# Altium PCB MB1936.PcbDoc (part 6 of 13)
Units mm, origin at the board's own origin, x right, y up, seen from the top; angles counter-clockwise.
Board outline 172 x 137 mm, 6 copper layers (Top Layer, Signal Layer 1, Signal Layer 2, Signal Layer 3, Signal Layer 4, Bottom Layer), stack 1.549 mm thick; 859 components, 672 nets, 3477 pads, 2222 vias.
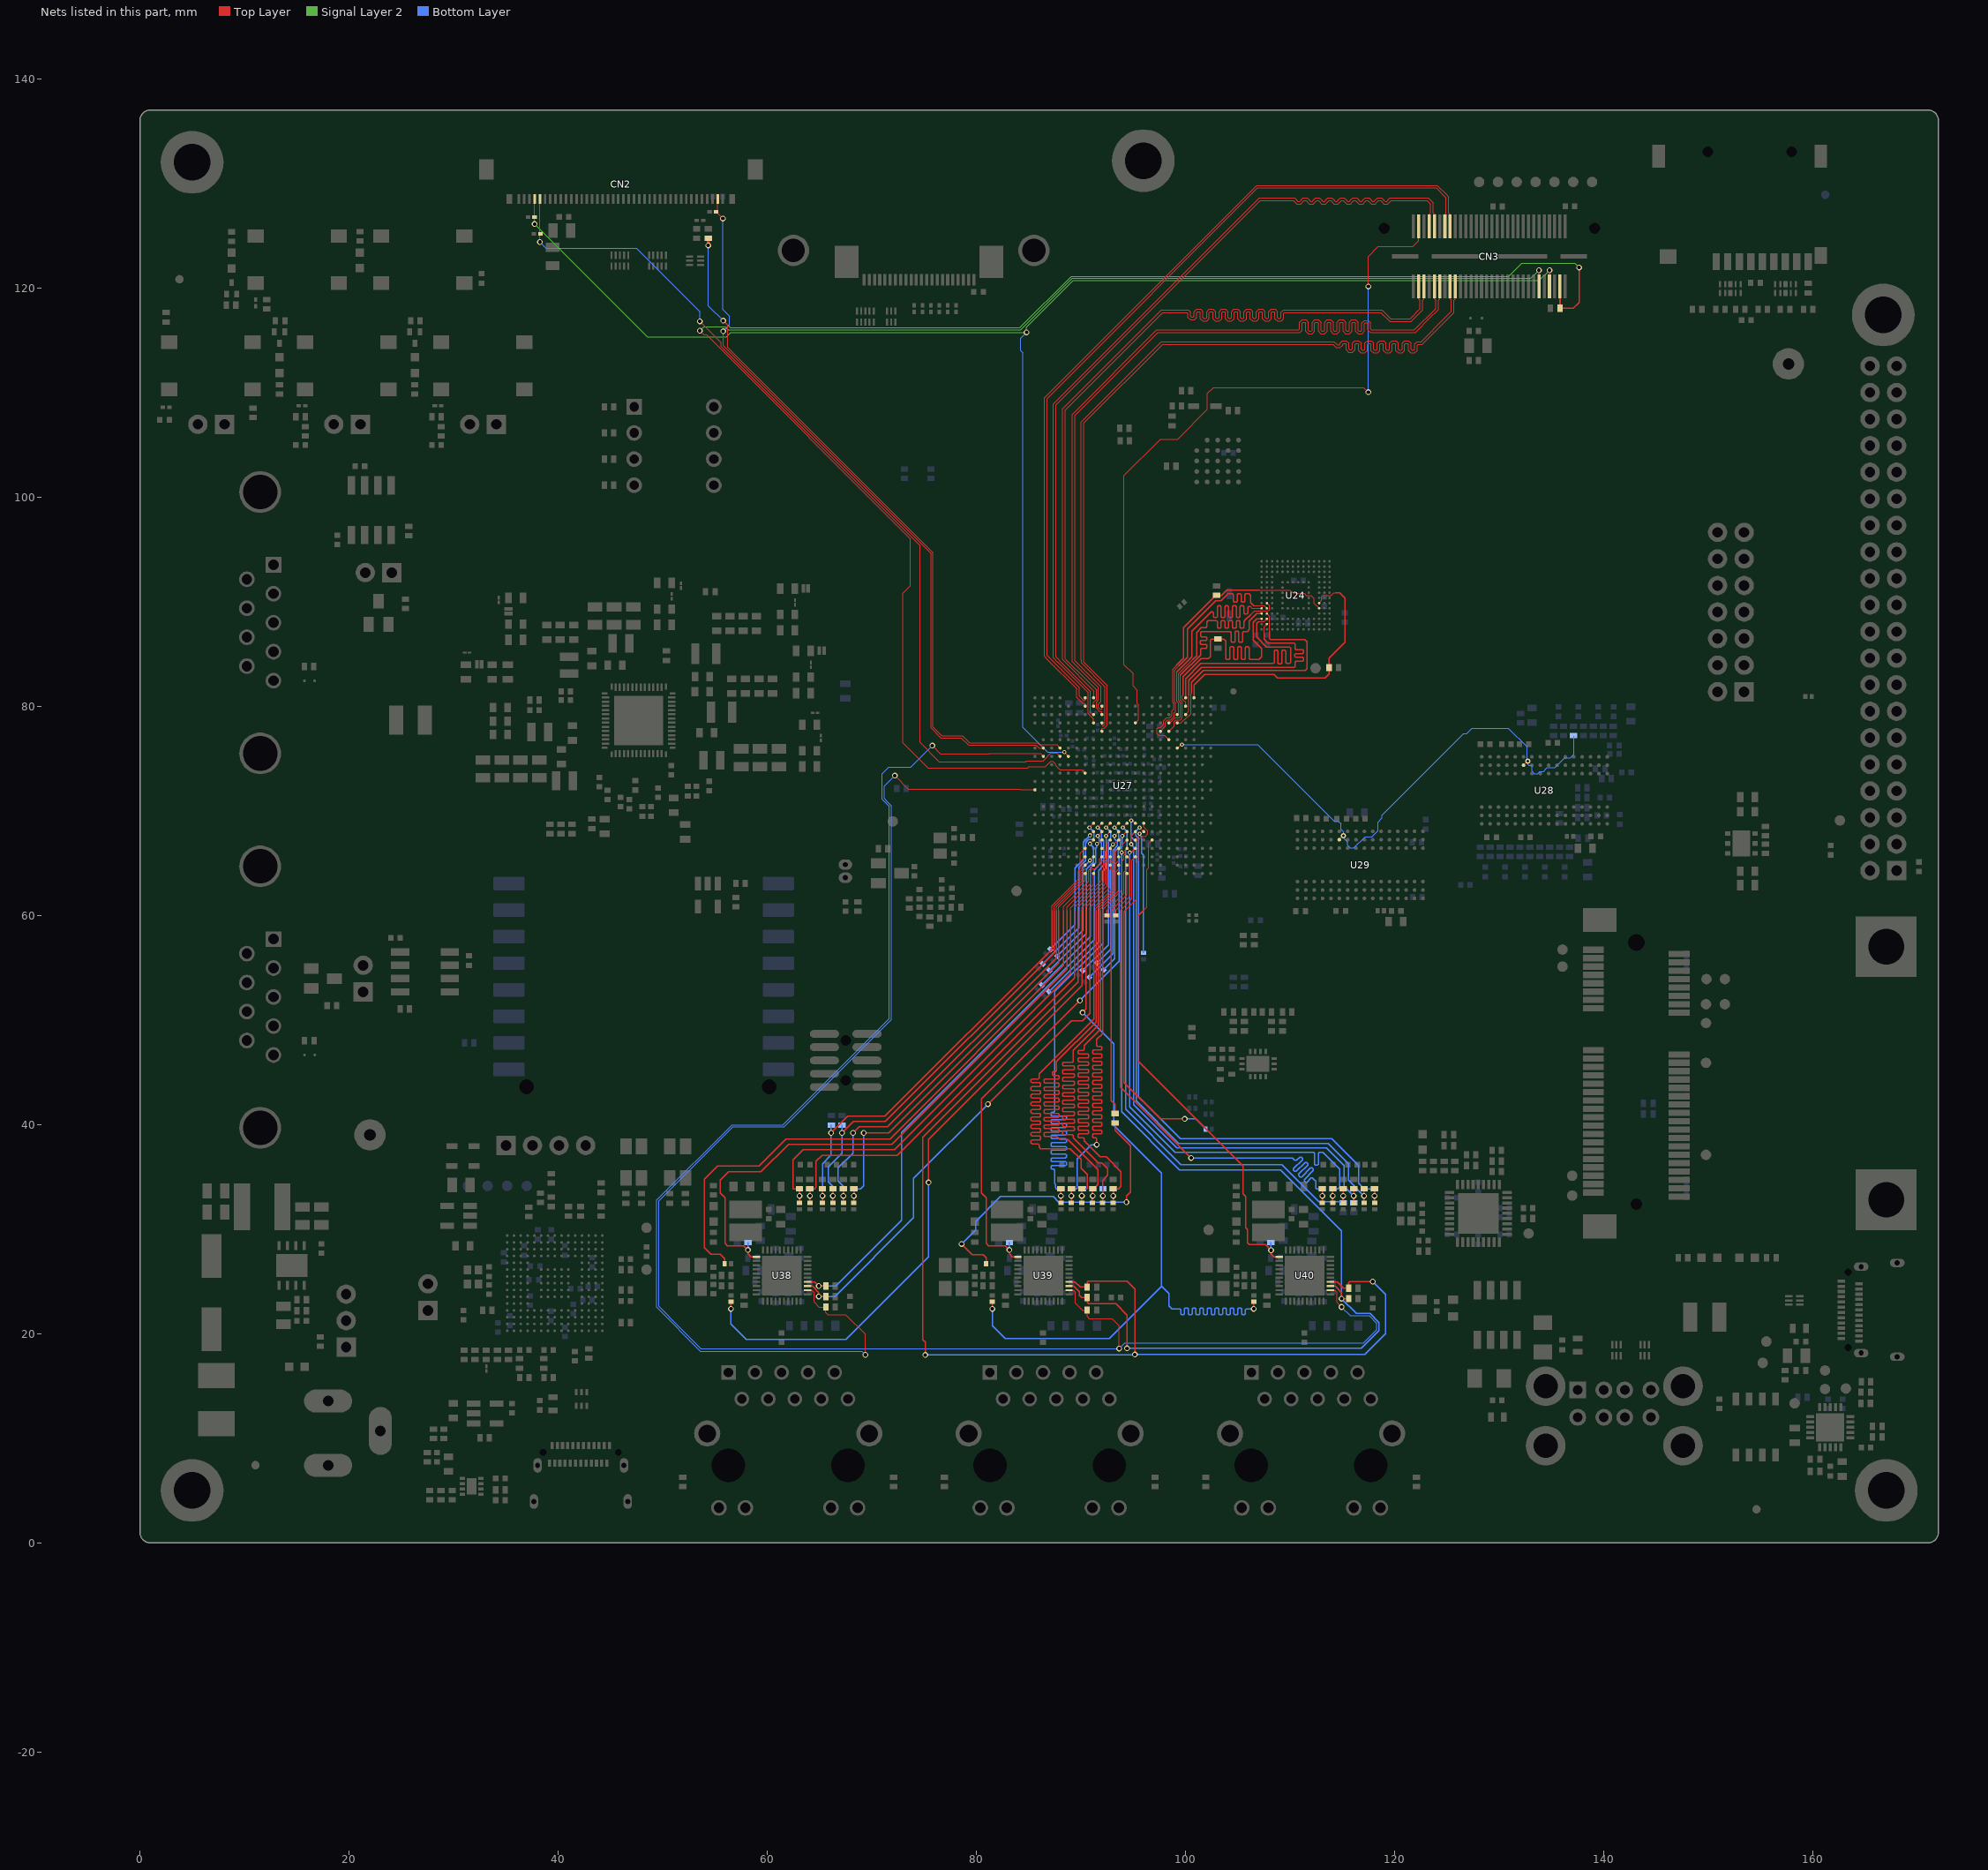
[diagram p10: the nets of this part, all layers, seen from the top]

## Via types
v1: diameter 0.55, hole 0.35, Top Layer to Bottom Layer, 1661 vias
v2: diameter 0.4, hole 0.2, Top Layer to Bottom Layer, tented both sides, 253 vias
v3: diameter 0.5, hole 0.2, Top Layer to Bottom Layer, 157 vias
v4: diameter 0.5, hole 0.25, Top Layer to Bottom Layer, 145 vias
v5: diameter 0.4, hole 0.2, Top Layer to Bottom Layer, 6 vias

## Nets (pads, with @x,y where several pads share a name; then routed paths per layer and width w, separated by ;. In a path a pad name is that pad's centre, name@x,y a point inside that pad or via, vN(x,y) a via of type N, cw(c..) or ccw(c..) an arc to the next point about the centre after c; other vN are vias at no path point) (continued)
DDR_WEN: R257.1 U27.G18 U28.L2 U29.L2 | length 55
  Top Layer w0.09: U27.G18@99.2,76 99.257,76 99.582,76.325 v2(99.65,76.325) ; U29.L2@114.694,67.222 114.694,67.27 v4@115.049,67.625 ; U28.L2@132.325,74.325 132.325,74.373 v4@132.68,74.728
  Bottom Layer w0.09: v2(99.65,76.325) 99.666,76.341 106.877,76.341 114.223,68.995 114.614,68.995 114.845,68.764 114.845,68.223 115.1,67.968 v4(115.1,67.625) ; v4@115.102,67.625 115.162,67.566 115.162,67.322 115.505,66.979 115.505,66.684 115.737,66.453 116.098,66.453 117.165,67.52 117.824,67.52 118.388,68.084 118.388,68.909 118.395,68.909 118.794,69.308 118.794,69.555 126.602,77.363 126.878,77.363 127.412,77.897 130.872,77.897 132.662,76.107 132.662,74.813 v4(132.725,74.75) 132.725,74.458 132.839,74.345 133.032,74.345 133.124,74.253 133.124,73.793 133.362,73.555 133.689,73.555 133.885,73.751 134.227,73.751 134.585,74.11 135.319,74.11 136.274,75.065 136.799,75.065 137.135,75.401 137.135,77.141 R257.1@137.1,77.175
DISP.BLCTRL: CN2.37 CN3.53 U2.1 U27.H5 | length 152
  Top Layer w0.1: v1(37.75,126.1) CN2.37@37.75,128.5 ; v2(88.4,75.6) U27.H5@88.8,75.2 ; CN3.53@134.8,120.13 v1(134.8,121.675)
  Signal Layer 2 w0.1: v1(37.75,126.1) 48.525,115.325 56.1,115.325 56.525,115.75 v1(84.8,115.75) 84.8,116.25 89.25,120.7 133.825,120.7 v1(134.8,121.675)
  Bottom Layer w0.1: v1(84.8,115.75) 84.225,115.175 84.225,113.999 84.45,113.774 84.45,77.955 86.806,75.6 v2(88.4,75.6)
DISP.DSI_INT: CN3.4 U27.D13 | length 72
  Top Layer w0.1: U27.D13@95.2,78.4 95.49,78.69 95.49,80.141 95.385,80.246 95.385,81.515 94.975,81.925 94.975,83.1 94.125,83.95 94.125,84.475 94.125,102.051 97.599,105.525 99.248,105.525 102.1,108.377 102.1,109.917 102.658,110.475 117.025,110.475 v1(117.475,110.025) ; v1(117.475,120.125) 117.475,123 118.42,123.945 121.72,123.945 122.3,124.525 CN3.4@122.3,125.87
  Bottom Layer w0.1: v1(117.475,110.025) v1(117.475,120.125)
DISP.LED_EN: CN2.36 U4.1 U27.H4 | length 86.7
  Top Layer w0.09: 81.172,74.685 84.727,74.685 84.787,74.745 86.364,74.745 86.796,75.177 86.796,75.213 87.088,75.505 87.695,75.505 U27.H4@88,75.2
  Top Layer w0.1: v1(38.25,124.375) 38.25,125.625 CN2.36@38.25,128.5 ; v1(53.55,116.8) 55.575,114.775 55.575,114.384 74.6,95.359 74.6,76.516 76.431,74.685 81.172,74.685
  Bottom Layer w0.1: v1(38.25,124.375) 38.85,123.775 47.475,123.775 53.55,117.7 v1(53.55,116.8)
DISP.LVDS_INT: CN2.2 U1.1 U27.G2 | length 71.1
  Top Layer w0.1: CN2.2@55.25,128.5 55.25,127.275 55.275,127.25 55.275,127.1 v1(55.75,126.625) ; v1(55.775,115.85) 55.775,114.467 75.65,94.592 75.65,77.94 76.615,76.975 78.55,76.975 79.235,76.29 81.172,76.29 85.72,76.29 86.01,76 U27.G2@86.4,76
  Bottom Layer w0.1: v1(55.75,126.625) 55.75,117.925 56.4,117.275 56.4,116.475 v1(55.775,115.85)
DISP.RESET: CN3.57 R2.1 R9.2 U27.G4 | length 161
  Top Layer w0.09: 81.172,76.49 85.834,76.49 86.009,76.315 87.685,76.315 U27.G4@88,76
  Top Layer w0.1: v1(55.775,116.85) 56.225,116.4 56.225,114.3 75.85,94.675 75.85,78.023 76.698,77.175 78.674,77.175 79.359,76.49 81.172,76.49
  Top Layer w0.15: CN3.57@135.8,120.13 R9.2@135.8,118.05 137.08,118.05 137.64,118.61 v1(137.64,121.95)
  Top Layer w0.3: v1(54.35,124.051) R2.1@54.35,124.745
  Signal Layer 2 w0.1: v1(55.775,116.85) 56.45,116.175 84.159,116.175 89.084,121.1 130.9,121.1 132.175,122.375 137.215,122.375 v1(137.64,121.95)
  Bottom Layer w0.1: v1@54.35,124.05 54.35,118.275 v1(55.775,116.85)
DISP.TE: CN3.49 U27.K7 | length 151.8
  Top Layer w0.09: 81.172,74.085 84.891,74.085 85.011,74.205 86.602,74.205 87.102,74.705 87.326,74.705 87.55,74.481 87.55,74.325
  Top Layer w0.1: v1(53.55,115.9) 53.95,115.5 54.175,115.5 73.678,95.997 73.678,91.518 72.975,90.814 72.975,76.5 75.39,74.085 81.172,74.085 ; 87.55,74.325 87.97,73.905 90.095,73.905 U27.K7@90.4,73.6 ; CN3.49@133.8,120.13 v1(133.8,121.675)
  Signal Layer 2 w0.1: v1(53.55,115.9) 53.925,116.275 55.951,116.275 56.251,115.975 84.242,115.975 89.167,120.9 133.025,120.9 v1(133.8,121.675)
DSI.CK_N: CN3.5 U27.B8 | length 81.7
  Top Layer w0.09: U27.B8@91.2,80 91.2,80.355 91.485,80.64 91.485,81.546 90.382,82.648 88.556,84.475 88.475,84.556 88.475,108.325 97.8,117.65 99.7,117.65 100.15,117.65 100.236,117.564 100.236,117.184 100.468,116.952 100.847,116.952 101.08,117.184 101.08,117.617 101.166,117.703 101.338,117.703 101.424,117.617 101.424,117.048 101.656,116.816 102.035,116.816 102.268,117.048 102.268,117.617 102.354,117.703 102.526,117.703 102.612,117.617 102.612,117.048 102.844,116.816 103.223,116.816 103.456,117.048 103.456,117.617 103.542,117.703 103.714,117.703 103.8,117.617 103.8,117.048 104.032,116.816 104.411,116.816 104.644,117.048 104.644,117.617 104.73,117.703 104.902,117.703 104.988,117.617 104.988,117.048 105.22,116.816 105.599,116.816 105.832,117.048 105.832,117.617 105.918,117.703 106.09,117.703 106.176,117.617 106.176,117.048 106.408,116.816 106.787,116.816 107.02,117.048 107.02,117.617 107.106,117.703 107.278,117.703 107.364,117.617 107.364,117.048 107.596,116.816 107.975,116.816 108.208,117.048 108.208,117.617 108.294,117.703 108.466,117.703 108.552,117.617 108.552,117.048 108.784,116.816 109.163,116.816 109.396,117.048 109.396,117.564 109.482,117.65 109.6,117.65 118.675,117.65 119.527,116.798 121.595,116.798 121.668,116.871 122.675,117.879 122.675,118.825 122.8,118.95 CN3.5@122.8,120.13
DSI.CK_P: CN3.3 U27.A8 | length 80.8
  Top Layer w0.09: U27.A8@91.2,80.8 U27.A8@91.235,80.835 ; U27.A8@91.235,80.836 91.235,81.442 88.225,84.452 88.225,84.475 88.225,84.659 88.225,108.429 97.696,117.9 99.7,117.9 100.253,117.9 100.486,117.668 100.486,117.288 100.572,117.202 100.744,117.202 100.83,117.288 100.83,117.72 101.062,117.953 101.441,117.953 101.674,117.72 101.674,117.152 101.76,117.066 101.932,117.066 102.018,117.152 102.018,117.72 102.25,117.953 102.629,117.953 102.862,117.72 102.862,117.152 102.948,117.066 103.12,117.066 103.206,117.152 103.206,117.72 103.438,117.953 103.817,117.953 104.05,117.72 104.05,117.152 104.136,117.066 104.308,117.066 104.394,117.152 104.394,117.72 104.626,117.953 105.005,117.953 105.238,117.72 105.238,117.152 105.324,117.066 105.496,117.066 105.582,117.152 105.582,117.72 105.814,117.953 106.193,117.953 106.426,117.72 106.426,117.152 106.512,117.066 106.684,117.066 106.77,117.152 106.77,117.72 107.002,117.953 107.381,117.953 107.614,117.72 107.614,117.152 107.7,117.066 107.872,117.066 107.958,117.152 107.958,117.72 108.19,117.953 108.569,117.953 108.802,117.72 108.802,117.152 108.888,117.066 109.06,117.066 109.146,117.152 109.146,117.668 109.378,117.9 109.6,117.9 118.779,117.9 119.63,117.048 121.491,117.048 121.646,117.204 122.309,117.866 122.425,117.982 122.425,118.825 122.3,118.95 CN3.3@122.3,120.13
DSI.D0_N: CN3.11 U27.B9 | length 81.4
  Top Layer w0.09: U27.B9@92,80 92,79.751 91.944,79.695 91.866,79.695 91.675,79.886 91.675,80.222 91.915,80.462 91.915,81.863 89.425,84.353 89.425,84.475 89.425,107.8 97.35,115.725 110.708,115.725 110.811,115.725 110.929,115.725 111.162,115.957 111.162,116.61 111.248,116.696 111.42,116.696 111.506,116.61 111.506,115.842 111.738,115.61 112.117,115.61 112.35,115.842 112.35,116.61 112.436,116.696 112.608,116.696 112.694,116.61 112.694,115.842 112.926,115.61 113.305,115.61 113.538,115.842 113.538,116.61 113.624,116.696 113.796,116.696 113.882,116.61 113.882,115.842 114.114,115.61 114.493,115.61 114.726,115.842 114.726,116.61 114.812,116.696 114.984,116.696 115.07,116.61 115.07,115.842 115.302,115.61 115.681,115.61 115.914,115.842 115.914,116.61 116,116.696 116.172,116.696 116.258,116.61 116.258,115.842 116.49,115.61 116.869,115.61 117.102,115.842 117.102,116.554 117.188,116.64 117.36,116.64 117.446,116.554 117.446,115.957 117.678,115.725 118.675,115.725 121.975,115.725 123.4,117.15 124.087,117.837 124.175,117.925 124.175,118.825 124.3,118.95 CN3.11@124.3,120.13
DSI.D0_P: CN3.9 U27.C9 | length 81.7
  Top Layer w0.09: U27.C9@92,79.2 92,79.449 91.944,79.505 91.787,79.505 91.485,79.807 91.485,80.385 91.665,80.565 91.665,81.76 89.175,84.25 89.175,84.475 89.175,107.904 97.246,115.975 109.708,115.975 110.708,115.975 110.826,115.975 110.912,116.061 110.912,116.714 111.144,116.946 111.523,116.946 111.756,116.714 111.756,115.946 111.842,115.86 112.014,115.86 112.1,115.946 112.1,116.714 112.332,116.946 112.711,116.946 112.944,116.714 112.944,115.946 113.03,115.86 113.202,115.86 113.288,115.946 113.288,116.714 113.52,116.946 113.899,116.946 114.132,116.714 114.132,115.946 114.218,115.86 114.39,115.86 114.476,115.946 114.476,116.714 114.708,116.946 115.087,116.946 115.32,116.714 115.32,115.946 115.406,115.86 115.578,115.86 115.664,115.946 115.664,116.714 115.896,116.946 116.275,116.946 116.508,116.714 116.508,115.946 116.594,115.86 116.766,115.86 116.852,115.946 116.852,116.658 117.084,116.89 117.463,116.89 117.696,116.658 117.696,116.061 117.782,115.975 118.675,115.975 121.871,115.975 123.925,118.029 123.925,118.825 123.8,118.95 CN3.9@123.8,120.13
DSI.D1_N: CN3.17 U27.E9 | length 81.8
  Top Layer w0.09: U27.E9@92,77.6 92,77.832 92.053,77.885 92.222,77.885 92.515,78.178 92.515,81.96 90.265,84.21 90.265,84.361 90.275,84.371 90.275,107.075 97.8,114.6 113.169,114.6 114.088,114.6 114.174,114.514 114.406,114.282 114.785,114.282 115.018,114.514 115.018,114.594 115.104,114.68 115.276,114.68 115.362,114.594 115.362,114.084 115.594,113.851 115.973,113.851 116.206,114.084 116.206,114.594 116.292,114.68 116.464,114.68 116.55,114.594 116.55,114.009 116.782,113.776 117.161,113.776 117.394,114.009 117.394,114.594 117.48,114.68 117.652,114.68 117.738,114.594 117.738,114.009 117.97,113.776 118.349,113.776 118.582,114.009 118.582,114.594 118.668,114.68 118.84,114.68 118.926,114.594 118.926,114.009 119.158,113.776 119.537,113.776 119.77,114.009 119.77,114.594 119.856,114.68 120.028,114.68 120.114,114.594 120.114,114.009 120.346,113.776 120.725,113.776 120.958,114.009 120.958,114.594 121.044,114.68 121.216,114.68 121.302,114.594 121.302,114.009 121.534,113.776 121.913,113.776 122.146,114.009 122.146,114.514 122.232,114.6 122.35,114.6 122.625,114.6 125.65,117.625 125.65,118.8 125.8,118.95 CN3.17@125.8,120.13
DSI.D1_P: CN3.15 U27.D9 | length 81.4
  Top Layer w0.09: U27.D9@92,78.4 92,78.168 92.053,78.115 92.127,78.115 92.285,78.273 92.285,81.865 90.035,84.115 90.035,84.361 90.025,84.371 90.025,107.179 97.696,114.85 113.169,114.85 114.191,114.85 114.424,114.618 114.51,114.532 114.682,114.532 114.768,114.618 114.768,114.697 115,114.93 115.379,114.93 115.612,114.697 115.612,114.187 115.698,114.101 115.87,114.101 115.956,114.187 115.956,114.697 116.188,114.93 116.567,114.93 116.8,114.697 116.8,114.112 116.886,114.026 117.058,114.026 117.144,114.112 117.144,114.697 117.376,114.93 117.755,114.93 117.988,114.697 117.988,114.112 118.074,114.026 118.246,114.026 118.332,114.112 118.332,114.697 118.564,114.93 118.943,114.93 119.176,114.697 119.176,114.112 119.262,114.026 119.434,114.026 119.52,114.112 119.52,114.697 119.752,114.93 120.131,114.93 120.364,114.697 120.364,114.112 120.45,114.026 120.622,114.026 120.708,114.112 120.708,114.697 120.94,114.93 121.319,114.93 121.552,114.697 121.552,114.112 121.638,114.026 121.81,114.026 121.896,114.112 121.896,114.618 122.128,114.85 122.35,114.85 122.521,114.85 124.868,117.197 125.298,117.627 125.4,117.729 125.4,118.85 125.3,118.95 CN3.15@125.3,120.13
DSI.D2_N: CN3.10 U27.D8 | length 81.7
  Top Layer w0.09: U27.D8@91.2,78.4 91.2,78.775 90.685,79.29 90.685,81.301 87.761,84.225 87.746,84.225 87.35,84.621 87.35,108.904 107.046,128.6 108.456,128.6 110.428,128.6 110.66,128.368 110.66,128.345 110.746,128.259 110.918,128.259 111.004,128.345 111.004,128.377 111.237,128.609 111.616,128.609 111.848,128.377 111.848,128.345 111.934,128.259 112.106,128.259 112.192,128.345 112.192,128.377 112.425,128.609 112.804,128.609 113.036,128.377 113.036,128.345 113.122,128.259 113.294,128.259 113.38,128.345 113.38,128.377 113.613,128.609 113.992,128.609 114.224,128.377 114.224,128.345 114.31,128.259 114.482,128.259 114.568,128.345 114.568,128.377 114.801,128.609 115.18,128.609 115.412,128.377 115.412,128.345 115.498,128.259 115.67,128.259 115.756,128.345 115.756,128.377 115.989,128.609 116.368,128.609 116.6,128.377 116.6,128.345 116.686,128.259 116.858,128.259 116.944,128.345 116.944,128.377 117.177,128.609 117.556,128.609 117.788,128.377 117.788,128.345 117.874,128.259 118.046,128.259 118.132,128.345 118.132,128.377 118.365,128.609 118.744,128.609 118.976,128.377 118.976,128.345 119.062,128.259 119.234,128.259 119.32,128.345 119.32,128.368 119.553,128.6 119.774,128.6 123.2,128.6 123.675,128.125 123.675,127.175 123.8,127.05 CN3.10@123.8,125.87
DSI.D2_P: CN3.8 U27.C8 | length 80
  Top Layer w0.09: U27.C8@91.2,79.2 91.16,79.24 91.06,79.24 90.915,79.386 90.915,81.396 87.923,84.388 87.923,84.402 87.85,84.475 87.6,84.725 87.6,108.8 107.15,128.35 108.456,128.35 110.324,128.35 110.41,128.264 110.41,128.242 110.643,128.009 111.022,128.009 111.254,128.242 111.254,128.273 111.34,128.359 111.512,128.359 111.598,128.273 111.598,128.242 111.831,128.009 112.21,128.009 112.442,128.242 112.442,128.273 112.528,128.359 112.7,128.359 112.786,128.273 112.786,128.242 113.019,128.009 113.398,128.009 113.63,128.242 113.63,128.273 113.716,128.359 113.888,128.359 113.974,128.273 113.974,128.242 114.207,128.009 114.586,128.009 114.818,128.242 114.818,128.273 114.904,128.359 115.076,128.359 115.162,128.273 115.162,128.242 115.395,128.009 115.774,128.009 116.006,128.242 116.006,128.273 116.092,128.359 116.264,128.359 116.35,128.273 116.35,128.242 116.583,128.009 116.962,128.009 117.194,128.242 117.194,128.273 117.28,128.359 117.452,128.359 117.538,128.273 117.538,128.242 117.771,128.009 118.15,128.009 118.382,128.242 118.382,128.273 118.468,128.359 118.64,128.359 118.726,128.273 118.726,128.242 118.959,128.009 119.338,128.009 119.57,128.242 119.57,128.264 119.656,128.35 119.774,128.35 120.022,128.35 123.075,128.35 123.096,128.35 123.425,128.021 123.425,127.175 123.3,127.05 CN3.8@123.3,125.87
DSI.D3_N: CN3.16 U27.B7 | length 81.6
  Top Layer w0.09: U27.B7@90.4,80 90.388,80.012 90.388,80.219 90.332,80.275 90.15,80.275 89.575,80.85 89.575,81.681 86.781,84.475 86.5,84.756 86.5,109.504 106.796,129.8 124.079,129.8 124.962,128.917 125.175,128.704 125.175,127.175 125.3,127.05 CN3.16@125.3,125.87
DSI.D3_P: CN3.14 U27.A7 | length 80.4
  Top Layer w0.09: U27.A7@90.4,80.8 90.388,80.788 90.388,80.581 90.332,80.525 90.253,80.525 89.825,80.953 89.825,81.785 87.135,84.475 86.75,84.86 86.75,109.4 106.9,129.55 123.975,129.55 124.785,128.74 124.925,128.6 124.925,127.425 124.925,127.175 124.8,127.05 CN3.14@124.8,125.87
eMMC.SDMMC2_CK: R49.1 U24.M6 U27.A20 | length 26.1
  Top Layer w0.09: U24.M6@112.775,89.85 113.025,90.1 113.025,90.454 113.171,90.6 113.925,90.6 114.175,90.85 114.375,90.85
  Top Layer w0.11: U27.A20@100.8,80.8 100.8,82.03 101.807,83.037 106.072,83.037 108.445,83.037 108.767,82.715 113.348,82.715 113.725,83.093 R49.1@113.725,83.685 113.725,84.582 115.25,86.107 115.25,90.35 114.75,90.85 114.375,90.85
eMMC.SDMMC2_CMD: R37.1 U24.M5 U27.F17 | length 28.4
  Top Layer w0.09: U27.F17@98.4,76.8 98.002,77.198 97.453,77.198 97.29,77.36 97.29,77.84 97.432,77.982 97.62,77.982 97.91,78.272 97.91,78.596 98.199,78.885 98.488,78.885 98.715,79.112 98.715,79.56 98.865,79.71 98.865,80.231 98.785,80.311 98.785,83.537 99.131,83.883 99.131,83.898 ; 107.071,91.1 109.975,91.1 110.3,90.775 111.35,90.775 111.525,90.6 112,90.6 112.3,90.3 112.3,89.825 U24.M5@112.775,89.35
  Top Layer w0.11: 99.124,83.891 99.131,83.898 99.185,83.952 99.185,83.966 99.694,84.475 99.787,84.568 99.787,87.507 102.287,90.007 102.88,90.6 R37.1@102.975,90.6 103.449,90.6 103.943,91.093 107.071,91.093
eMMC.SDMMC2_D0: R44.1 U24.A3 U27.B19 | length 25.9
  Top Layer w0.09: 99.75,81.05 99.695,80.995 99.695,80.674 100,80.369 U27.B19@100,80
  Top Layer w0.11: 99.75,81.05 99.75,82.8 101.491,84.541 102.178,84.541 102.363,84.725 102.363,86.308 102.482,86.428 R44.1@103.1,86.428 103.633,86.428 103.836,86.225 103.836,84.57 103.929,84.477 ; 103.932,84.474 103.929,84.477 ; U24.A3@107.275,88.35 106.824,88.35 106.475,88.001 106.475,86.332 107.27,85.537 107.27,84.724 107.023,84.477 106.406,84.477 106.162,84.477 106.071,84.568 106.071,85.579 105.98,85.67 105.798,85.67 105.707,85.579 105.707,84.566 105.616,84.475 105.434,84.475 105.343,84.566 105.343,85.593 105.252,85.684 105.07,85.684 104.979,85.593 104.979,84.566 104.888,84.475 104.706,84.475 104.615,84.566 104.615,85.593 104.524,85.684 104.342,85.684 104.251,85.593 104.251,84.568 104.16,84.477 104.105,84.477 103.929,84.477
eMMC.SDMMC2_D1: U24.A4 U27.E17 | length 24
  Top Layer w0.09: U27.E17@98.4,77.6 98.895,78.095 98.895,78.526 99.074,78.705 99.505,78.705 99.695,78.895 99.695,80.419 99.515,80.599 99.515,82.965 99.525,82.975
  Top Layer w0.11: 99.525,82.965 99.525,82.975 101.442,84.892 101.442,85.031 101.442,85.45 101.533,85.541 101.944,85.541 102.035,85.632 102.035,85.814 101.944,85.905 101.493,85.905 101.402,85.996 101.402,86.178 101.493,86.269 101.944,86.269 102.035,86.36 102.035,86.542 101.944,86.633 101.533,86.633 101.442,86.724 101.442,86.911 101.442,87.057 101.525,87.14 103.849,87.14 104.268,87.14 104.359,87.049 104.359,86.182 104.45,86.091 104.632,86.091 104.723,86.182 104.723,87.061 104.814,87.152 104.996,87.152 105.087,87.061 105.087,86.182 105.178,86.091 105.36,86.091 105.451,86.182 105.451,87.049 105.542,87.14 105.917,87.14 105.923,87.146 106.102,87.325 106.102,88.132 106.82,88.85 U24.A4@107.275,88.85
eMMC.SDMMC2_D2: U24.A5 U27.C18 | length 25.1
  Top Layer w0.09: 99.155,83.28 99.155,80.45 99.335,80.27 99.335,79.361 99.2,79.226 U27.C18@99.2,79.2 ; 106.195,89.516 106.353,89.358 107.267,89.358 U24.A5@107.275,89.35
  Top Layer w0.11: 99.155,83.28 100.606,84.731 100.606,87.166 102.247,88.807 102.446,89.006 102.575,89.006 102.666,88.915 102.666,88.55 102.757,88.459 102.939,88.459 103.03,88.55 103.03,89.502 103.121,89.593 103.303,89.593 103.394,89.502 103.394,88.55 103.485,88.459 103.667,88.459 103.758,88.55 103.758,89.502 103.849,89.593 104.031,89.593 104.122,89.502 104.122,88.55 104.213,88.459 104.395,88.459 104.486,88.55 104.486,89.502 104.577,89.593 104.759,89.593 104.85,89.502 104.85,88.55 104.941,88.459 105.123,88.459 105.214,88.55 105.214,89.502 105.305,89.593 105.487,89.593 105.578,89.502 105.578,88.917 105.669,88.826 105.851,88.826 105.942,88.917 105.942,89.425 106.033,89.516 106.103,89.516 106.195,89.516
eMMC.SDMMC2_D3: U24.B2 U27.C19 | length 23.9
  Top Layer w0.09: U27.C19@100,79.2 100.31,79.51 100.31,81.055 ; 107.525,86.9 107.525,87.6 U24.B2@107.775,87.85
  Top Layer w0.11: 100.31,81.055 100.299,81.065 100.299,82.474 101.545,83.72 110.396,83.72 110.461,83.784 110.461,83.796 110.461,84.215 110.552,84.306 111.194,84.306 111.285,84.397 111.285,84.579 111.194,84.67 110.539,84.67 110.448,84.761 110.448,84.943 110.539,85.034 111.194,85.034 111.285,85.125 111.285,85.307 111.194,85.398 110.552,85.398 110.461,85.489 110.461,85.916 110.461,85.974 110.396,86.038 107.887,86.038 107.525,86.4 107.525,86.9
eMMC.SDMMC2_D4: U24.B3 U27.A19 | length 24.8
  Top Layer w0.09: 107,88.1 107.525,88.1 U24.B3@107.775,88.35
  Top Layer w0.11: U27.A19@100,80.8 100,82.625 101.459,84.084 108.332,84.084 108.387,84.084 108.478,84.175 108.478,85.263 108.569,85.354 108.751,85.354 108.842,85.263 108.842,84.122 108.933,84.031 109.115,84.031 109.206,84.122 109.206,85.263 109.297,85.354 109.479,85.354 109.57,85.263 109.57,84.175 109.661,84.084 109.866,84.084 109.947,84.084 110.053,84.19 110.053,85.549 109.938,85.664 107.753,85.664 106.814,86.603 106.814,87.914 107,88.1
eMMC.SDMMC2_D5: U24.B4 U27.D18 | length 25.1
  Top Layer w0.09: U27.D18@99.2,78.4 99.562,78.4 99.872,78.71 99.948,78.71 100.49,79.252 100.51,79.272 100.51,81.16 100.55,81.2 ; U24.B4@107.775,88.85 108.025,88.6 108.025,87.75 108.025,87.15
  Top Layer w0.11: 100.55,81.2 100.55,82.275 101.684,83.409 106.072,83.409 111.428,83.409 111.596,83.577 111.596,86.171 111.422,86.345 108.142,86.345 108.025,86.462 108.025,87.15
eMMC.SDMMC2_D6: U24.B5 U27.E16 | length 23.9
  Top Layer w0.09: U27.E16@97.6,77.6 98.09,78.09 98.09,78.375 98.095,78.38 98.095,78.526 98.274,78.705 98.563,78.705 98.895,79.037 98.895,79.345 99.045,79.495 99.045,80.305 98.965,80.385 98.965,83.463 99.385,83.883 ; 106.499,89.612 106.803,89.612 106.815,89.6 107.525,89.6 U24.B5@107.775,89.35
  Top Layer w0.11: 99.385,83.883 99.977,84.475 100.173,84.671 100.173,87.357 102.876,90.06 103.393,90.06 104.072,90.739 104.491,90.739 104.582,90.648 104.582,90.022 104.673,89.931 104.855,89.931 104.946,90.022 104.946,90.659 105.037,90.75 105.219,90.75 105.31,90.659 105.31,90.022 105.401,89.931 105.583,89.931 105.674,90.022 105.674,90.648 105.765,90.739 106.071,90.739 106.179,90.63 106.195,90.615 106.195,89.916 106.499,89.612
eMMC.SDMMC2_D7: U24.B6 U27.D17 | length 24
  Top Layer w0.09: U27.D17@98.4,78.4 98.44,78.44 98.552,78.44 98.997,78.885 99.431,78.885 99.515,78.969 99.515,80.345 99.335,80.525 99.335,83.11 100.7,84.475 ; 106.195,88.716 106.579,89.1 107.879,89.1 108.025,89.246 108.025,89.6 U24.B6@107.775,89.85
  Top Layer w0.11: 100.7,84.475 101.049,84.824 101.049,87.051 101.524,87.526 101.95,87.525 102.049,87.624 102.049,88.051 102.171,88.172 102.52,88.172 102.939,88.172 103.03,88.081 103.03,87.56 103.121,87.469 103.303,87.469 103.394,87.56 103.394,88.107 103.485,88.198 103.667,88.198 103.758,88.107 103.758,87.56 103.849,87.469 104.031,87.469 104.122,87.56 104.122,88.107 104.213,88.198 104.395,88.198 104.486,88.107 104.486,87.56 104.577,87.469 104.759,87.469 104.85,87.56 104.85,88.107 104.941,88.198 105.123,88.198 105.214,88.107 105.214,87.56 105.305,87.469 105.487,87.469 105.578,87.56 105.578,88.099 105.726,88.247 106.195,88.716
ETH1.CLK: R197.1 R198.1 U27.W10 | length 88.4
  Top Layer w0.09: 90.484,60.475 90.484,60.799 92.505,62.82 92.505,64.922 92.678,65.095 92.969,65.095 93.12,65.247 93.12,66.08 U27.W10@92.8,66.4
  Top Layer w0.11: v1(81.525,22.375) R197.1@81.525,23.05 ; v1(90.15,50.7) 90.484,51.034 90.484,60.475 ; v1(106.525,22.375) R198.1@106.525,23.05
  Bottom Layer w0.11: v1(81.525,22.375) 81.525,20.775 82.775,19.525 92.7,19.525 97.704,24.529 97.704,24.558 ; v1(90.15,50.7) 93.15,47.7 93.15,39.9 97.704,35.346 97.704,24.558 ; v1(106.525,22.375) 105.95,22.375 105.814,22.375 105.723,22.284 105.723,21.889 105.632,21.798 105.45,21.798 105.359,21.889 105.359,22.366 105.268,22.457 105.086,22.457 104.995,22.366 104.995,21.889 104.904,21.798 104.722,21.798 104.631,21.889 104.631,22.366 104.54,22.457 104.358,22.457 104.267,22.366 104.267,21.889 104.176,21.798 103.994,21.798 103.903,21.889 103.903,22.366 103.812,22.457 103.63,22.457 103.539,22.366 103.539,21.889 103.448,21.798 103.266,21.798 103.175,21.889 103.175,22.366 103.084,22.457 102.902,22.457 102.811,22.366 102.811,21.889 102.72,21.798 102.538,21.798 102.447,21.889 102.447,22.366 102.356,22.457 102.174,22.457 102.083,22.366 102.083,21.889 101.992,21.798 101.81,21.798 101.719,21.889 101.719,22.366 101.628,22.457 101.446,22.457 101.355,22.366 101.355,21.889 101.264,21.798 101.082,21.798 100.991,21.889 100.991,22.366 100.9,22.457 100.718,22.457 100.627,22.366 100.627,21.889 100.536,21.798 100.354,21.798 100.263,21.889 100.263,22.366 100.172,22.457 99.99,22.457 99.899,22.366 99.899,21.889 99.808,21.798 99.626,21.798 99.535,21.889 99.535,22.284 99.444,22.375 99.025,22.375 98.7,22.375 98.406,22.669 98.406,23.856 97.704,24.558
ETH1.CLK125: R93.1 U27.AB12 | length 23.7
  Top Layer w0.09: 92.9,60.475 94.4,61.975 U27.AB12@94.4,64
  Top Layer w0.11: 92.9,60.475 92.9,43.15 92.9,42.275 93.25,41.925 R93.1@93.25,41.05
ETH1.GTX_CLK: R162.1 U27.AA12 | length 5.6
  Top Layer w0.09: 92.475,60.475 94.105,62.105 94.105,64.122 94.4,64.417 U27.AA12@94.4,64.8
  Top Layer w0.11: R162.1@92.475,60 92.475,60.475
ETH1.MDC: R202.1 R203.1 U27.V12 U39.13 U40.13 | length 101.5
  Top Layer w0.09: v2(93.898,66.003) 93.93,66.035 93.93,66.75 94.38,67.2 U27.V12@94.4,67.2
  Top Layer w0.11: U39.13@88.85,24.55 89.312,24.55 89.85,24.012 89.85,23.675 90.075,23.45 R202.1@90.595,23.45 90.595,23.005 90.75,22.85 93.325,22.85 94.405,21.77 v1(94.405,18.585) ; U40.13@113.85,24.55 114.312,24.55 114.92,23.942 v1(114.92,23.35) R203.1@115.595,23.35
  Bottom Layer w0.11: v2(93.898,66.003) 93.898,60.475 93.898,41.202 99.435,35.665 109.081,35.665 114.92,29.826 v1(114.92,23.35) 116.35,21.92 117.652,21.92 118.51,21.062 118.51,20.288 116.807,18.585 v1(94.405,18.585)
ETH1.MDINT: R316.1 U27.U12 U39.31 | length 49.9
  Top Layer w0.09: v2(93.95,67.6) 94.35,68 U27.U12@94.4,68
  Top Layer w0.11: U39.31@83.95,27.35 83.45,27.35 83.176,27.624 83.176,27.974 82.737,28.413 81.169,28.413 80.955,28.627 80.955,32.975 80.485,33.445 80.485,42.435 v1(89.9,51.85)
  Bottom Layer w0.11: v1(83.15,28) R316.1@83.15,28.725 ; v1(89.9,51.85) 93.655,55.605 93.655,65.666 93.543,65.779 93.543,66.15 93.95,66.557 v2(93.95,67.6)
ETH1.MDIO: R192.1 R193.1 U27.V10 U39.14 U40.14 | length 125.4
  Top Layer w0.09: 89.73,60.475 89.73,60.789 92.145,63.204 92.145,65.071 92.505,65.431 92.505,65.722 92.505,66.905 U27.V10@92.8,67.2
  Top Layer w0.11: v1(75.1,17.954) 75.1,19.175 74.875,19.4 74.875,38.775 89.73,53.63 89.73,60.475 ; U39.14@88.85,24.95 89.42,24.95 89.92,24.45 R192.1@90.595,24.45 ; R192.1@90.595,24.55 90.595,24.926 90.674,25.005 94.39,25.005 95.15,24.245 v1(95.15,18) ; U40.14@113.85,24.95 114.52,24.95 115.12,24.35 R193.1@115.595,24.35 115.595,24.845 115.725,24.975 v1(117.9,24.975)
  Bottom Layer w0.11: v1(75.1,17.954) 75.123,17.977 95.127,17.977 v1(95.15,18) 117.125,18 119.125,20 119.125,23.75 v1(117.9,24.975)
ETH1.NRST: R206.1 U27.M1 U39.12 U40.12 | length 164.9
  Top Layer w0.09: 84.174,72.075 84.249,72
  Top Layer w0.1: v1(72.201,73.35) 73.476,72.075 84.174,72.075 ; 84.249,72 U27.M1@85.6,72 ; U39.12@88.85,24.15 89.275,24.15 89.48,23.945 89.48,22.89 90.12,22.25 R206.1@90.595,22.25 90.595,21.63 90.775,21.45 92.95,21.45 93.655,20.745 v1(93.655,18.575) ; U40.12@113.85,24.15 114.275,24.15 114.48,23.945 114.48,22.99 v1(114.92,22.55)
  Bottom Layer w0.1: v1(72.201,73.35) 71.191,72.341 71.191,71.157 71.462,70.887 71.87,70.479 71.87,50.046 61.599,39.775 56.722,39.775 49.625,32.678 49.625,22.597 51.594,20.628 53.647,18.575 v1(93.655,18.575) 94.18,19.1 117.025,19.1 118.3,20.375 118.3,20.975 117.565,21.71 115.76,21.71 v1(114.92,22.55)
ETH1.RX_CLK: R115.1 R141.1 R302.2 U27.U10 | length 58.4
  Top Layer w0.1: v2(92.4,67.6) U27.U10@92.8,68
  Top Layer w0.11: R141.1@88.075,32.5 v1(88.075,33.175) R115.1@88.075,33.85
  Bottom Layer w0.11: v1(88.075,33.175) R302.2@88.075,33.85 87.614,33.85 87.55,33.914 87.55,34.3 87.5,34.35 87.5,35.57 87.5,35.625 87.409,35.716 87.234,35.716 87.143,35.807 87.143,35.989 87.234,36.08 88.514,36.08 88.605,36.171 88.605,36.353 88.514,36.444 87.234,36.444 87.143,36.535 87.143,36.717 87.234,36.808 88.514,36.808 88.605,36.899 88.605,37.081 88.514,37.172 87.234,37.172 87.143,37.263 87.143,37.445 87.234,37.536 88.514,37.536 88.605,37.627 88.605,37.809 88.514,37.9 87.234,37.9 87.143,37.991 87.143,38.173 87.234,38.264 88.514,38.264 88.605,38.355 88.605,38.537 88.514,38.628 87.234,38.628 87.143,38.719 87.143,38.901 87.234,38.992 88.514,38.992 88.605,39.083 88.605,39.265 88.514,39.356 87.234,39.356 87.143,39.447 87.143,39.629 87.234,39.72 88.514,39.72 88.605,39.811 88.605,39.993 88.514,40.084 87.234,40.084 87.143,40.175 87.143,40.357 87.234,40.448 88.514,40.448 88.605,40.539 88.605,40.721 88.514,40.812 87.234,40.812 87.143,40.903 87.143,41.085 87.234,41.176 87.409,41.176 87.5,41.267 87.5,41.5 87.5,52.725 92.08,57.305 92.08,64.223 92.4,64.542 v2(92.4,67.6)
ETH1.RX_CTL: R116.1 R142.1 R301.2 U27.W12 | length 56.3
  Top Layer w0.09: 92.059,60.475 92.059,60.559 93.925,62.425 93.925,65.173 94.105,65.353 94.105,65.722 94.25,65.868 94.25,66.239 94.4,66.389 U27.W12@94.4,66.4
  Top Layer w0.11: R142.1@89.075,32.5 R116.1@89.075,33.85 ; v1(91.5,38.075) 91.5,38.591 91.5,38.646 91.409,38.737 91.201,38.737 91.11,38.828 91.11,39.01 91.201,39.101 91.918,39.101 92.009,39.192 92.009,39.374 91.918,39.465 91.201,39.465 91.11,39.556 91.11,39.738 91.201,39.829 91.918,39.829 92.009,39.92 92.009,40.102 91.918,40.193 91.201,40.193 91.11,40.284 91.11,40.466 91.201,40.557 91.918,40.557 92.009,40.648 92.009,40.83 91.918,40.921 91.201,40.921 91.11,41.012 91.11,41.194 91.201,41.285 91.918,41.285 92.009,41.376 92.009,41.558 91.918,41.649 91.201,41.649 91.11,41.74 91.11,41.922 91.201,42.013 91.918,42.013 92.009,42.104 92.009,42.286 91.918,42.377 91.201,42.377 91.11,42.468 91.11,42.65 91.201,42.741 91.918,42.741 92.009,42.832 92.009,43.014 91.918,43.105 91.201,43.105 91.11,43.196 91.11,43.378 91.201,43.469 91.918,43.469 92.009,43.56 92.009,43.742 91.918,43.833 91.201,43.833 91.11,43.924 91.11,44.106 91.201,44.197 91.918,44.197 92.009,44.288 92.009,44.47 91.918,44.561 91.201,44.561 91.11,44.652 91.11,44.834 91.201,44.925 91.918,44.925 92.009,45.016 92.009,45.198 91.918,45.289 91.201,45.289 91.11,45.38 91.11,45.562 91.201,45.653 91.918,45.653 92.009,45.744 92.009,45.926 91.918,46.017 91.201,46.017 91.11,46.108 91.11,46.29 91.201,46.381 91.918,46.381 92.009,46.472 92.009,46.654 91.918,46.745 91.201,46.745 91.11,46.836 91.11,47.018 91.201,47.109 91.918,47.109 92.009,47.2 92.009,47.382 91.918,47.473 91.591,47.473 91.5,47.564 91.5,47.7 91.5,48.125 92.059,48.684 92.059,60.475
  Bottom Layer w0.11: v1(89.075,33.175) R301.2@89.075,33.85 89.561,33.85 89.625,33.914 89.625,36.7 91,38.075 v1(91.5,38.075)
ETH1.RXD0: R117.1 R143.1 R296.2 U27.W11 | length 56.3
  Top Layer w0.09: 91.219,60.475 91.219,60.751 92.945,62.477 92.945,64.271 93.125,64.451 93.125,64.997 93.3,65.172 93.3,66.1 U27.W11@93.6,66.4
  Top Layer w0.11: R143.1@90.075,32.5 v1(90.075,33.175) R117.1@90.075,33.85 90.536,33.85 90.6,33.914 90.6,35.225 90,35.825 90,36.65 88.975,37.675 86.15,37.675 85.987,37.838 85.987,38.014 85.987,38.069 85.897,38.16 85.308,38.16 85.217,38.251 85.217,38.433 85.308,38.524 86.056,38.524 86.147,38.615 86.147,38.797 86.056,38.888 85.308,38.888 85.217,38.979 85.217,39.161 85.308,39.252 86.056,39.252 86.147,39.343 86.147,39.525 86.056,39.616 85.308,39.616 85.217,39.707 85.217,39.889 85.308,39.98 86.056,39.98 86.147,40.071 86.147,40.253 86.056,40.344 85.308,40.344 85.217,40.435 85.217,40.617 85.308,40.708 86.056,40.708 86.147,40.799 86.147,40.981 86.056,41.072 85.308,41.072 85.217,41.163 85.217,41.345 85.308,41.436 86.056,41.436 86.147,41.527 86.147,41.709 86.056,41.8 85.308,41.8 85.217,41.891 85.217,42.073 85.308,42.164 86.056,42.164 86.147,42.255 86.147,42.437 86.056,42.528 85.308,42.528 85.217,42.619 85.217,42.801 85.308,42.892 86.056,42.892 86.147,42.983 86.147,43.165 86.056,43.256 85.308,43.256 85.217,43.347 85.217,43.529 85.308,43.62 86.056,43.62 86.147,43.711 86.147,43.893 86.056,43.984 85.308,43.984 85.217,44.075 85.217,44.257 85.308,44.348 85.897,44.348 85.987,44.439 85.987,44.55 85.987,44.837 91.219,50.069 91.219,60.475
  Bottom Layer w0.11: v1(90.075,33.175) 90.075,33.775 R296.2@90.15,33.85
ETH1.RXD1: R108.1 R144.1 R295.2 U27.Y11 | length 60.2
  Top Layer w0.09: 91.429,60.475 91.429,60.707 93.125,62.403 93.125,64.197 93.305,64.377 93.305,64.922 93.6,65.217 U27.Y11@93.6,65.6
  Top Layer w0.11: R144.1@91.075,32.5 91.075,33.175 91.125,33.225 R108.1@91.125,33.85 91.22,33.85 91.63,34.26 91.63,35.685 88.765,38.55 87.975,38.55 87.8,38.725 87.654,38.871 86.573,38.871 86.482,38.962 86.482,39.144 86.573,39.235 87.804,39.235 87.895,39.326 87.895,39.508 87.804,39.599 86.573,39.599 86.482,39.69 86.482,39.872 86.573,39.963 87.804,39.963 87.895,40.054 87.895,40.236 87.804,40.327 86.573,40.327 86.482,40.418 86.482,40.6 86.573,40.691 87.804,40.691 87.895,40.782 87.895,40.964 87.804,41.055 86.573,41.055 86.482,41.146 86.482,41.328 86.573,41.419 87.804,41.419 87.895,41.51 87.895,41.692 87.804,41.783 86.573,41.783 86.482,41.874 86.482,42.056 86.573,42.147 87.804,42.147 87.895,42.238 87.895,42.42 87.804,42.511 86.573,42.511 86.482,42.602 86.482,42.784 86.573,42.875 87.804,42.875 87.895,42.966 87.895,43.148 87.804,43.239 86.573,43.239 86.482,43.33 86.482,43.512 86.573,43.603 87.804,43.603 87.895,43.694 87.895,43.876 87.804,43.967 86.573,43.967 86.482,44.058 86.482,44.24 86.573,44.331 87.804,44.331 87.895,44.422 87.895,44.604 87.804,44.695 87.355,44.695 87.264,44.786 87.264,44.968 87.355,45.059 87.572,45.059 87.663,45.15 87.663,45.375 87.663,46.038 91.429,49.804 91.429,60.475
  Bottom Layer w0.11: v1(91.125,33.175) R295.2@91.125,33.85
ETH1.RXD2: R145.1 R294.2 U27.AA11 | length 57.3
  Top Layer w0.09: 91.639,60.475 91.639,60.662 93.305,62.328 93.305,64.122 93.6,64.417 U27.AA11@93.6,64.8
  Top Layer w0.11: 91.639,60.475 91.639,49.489 89.25,47.1 89.25,46.8 89.25,46.046 89.159,45.955 88.328,45.955 88.237,45.864 88.237,45.682 88.328,45.591 89.304,45.591 89.395,45.5 89.395,45.318 89.304,45.227 88.328,45.227 88.237,45.136 88.237,44.954 88.328,44.863 89.304,44.863 89.395,44.772 89.395,44.59 89.304,44.499 88.328,44.499 88.237,44.408 88.237,44.226 88.328,44.135 89.304,44.135 89.395,44.044 89.395,43.862 89.304,43.771 88.328,43.771 88.237,43.68 88.237,43.498 88.328,43.407 89.304,43.407 89.395,43.316 89.395,43.134 89.304,43.043 88.328,43.043 88.237,42.952 88.237,42.77 88.328,42.679 89.304,42.679 89.395,42.588 89.395,42.406 89.304,42.315 88.328,42.315 88.237,42.224 88.237,42.042 88.328,41.951 89.304,41.951 89.395,41.86 89.395,41.678 89.304,41.587 88.328,41.587 88.237,41.496 88.237,41.314 88.328,41.223 89.304,41.223 89.395,41.132 89.395,40.95 89.304,40.859 88.328,40.859 88.237,40.768 88.237,40.586 88.328,40.495 89.304,40.495 89.395,40.404 89.395,40.222 89.304,40.131 88.328,40.131 88.237,40.04 88.237,39.858 88.328,39.767 89.304,39.767 89.395,39.676 89.395,39.494 89.304,39.403 88.328,39.403 88.237,39.312 88.237,39.13 88.328,39.039 89.159,39.039 89.25,38.948 89.25,38.893 89.25,38.75 91.675,36.325 92,36.325 92.55,35.775 92.55,35.128 92.075,34.653 92.075,33.175 R145.1@92.075,32.5
  Bottom Layer w0.11: v1(92.1,33.175) R294.2@92.1,33.85
ETH1.RXD3: R118.1 R146.1 R300.2 U27.AB11 | length 56.6
  Top Layer w0.09: 91.849,60.475 91.849,60.618 93.6,62.369 U27.AB11@93.6,64
  Top Layer w0.11: 91.849,60.475 91.849,49.099 90.3,47.55 90.3,47.3 90.3,47.191 90.209,47.1 89.82,47.1 89.729,47.009 89.729,46.827 89.82,46.736 90.643,46.736 90.734,46.645 90.734,46.463 90.643,46.372 89.82,46.372 89.729,46.281 89.729,46.099 89.82,46.008 90.643,46.008 90.734,45.917 90.734,45.735 90.643,45.644 89.82,45.644 89.729,45.553 89.729,45.371 89.82,45.28 90.643,45.28 90.734,45.189 90.734,45.007 90.643,44.916 89.82,44.916 89.729,44.825 89.729,44.643 89.82,44.552 90.643,44.552 90.734,44.461 90.734,44.279 90.643,44.188 89.82,44.188 89.729,44.097 89.729,43.915 89.82,43.824 90.643,43.824 90.734,43.733 90.734,43.551 90.643,43.46 89.82,43.46 89.729,43.369 89.729,43.187 89.82,43.096 90.643,43.096 90.734,43.005 90.734,42.823 90.643,42.732 89.82,42.732 89.729,42.641 89.729,42.459 89.82,42.368 90.643,42.368 90.734,42.277 90.734,42.095 90.643,42.004 89.82,42.004 89.729,41.913 89.729,41.731 89.82,41.64 90.643,41.64 90.734,41.549 90.734,41.367 90.643,41.276 89.82,41.276 89.729,41.185 89.729,41.003 89.82,40.912 90.643,40.912 90.734,40.821 90.734,40.639 90.643,40.548 89.82,40.548 89.729,40.457 89.729,40.275 89.82,40.184 90.643,40.184 90.734,40.093 90.734,39.911 90.643,39.82 89.82,39.82 89.729,39.729 89.729,39.547 89.82,39.456 90.643,39.456 90.734,39.365 90.734,39.183 90.643,39.092 89.82,39.092 89.729,39.001 89.729,38.819 89.82,38.728 90.209,38.728 90.3,38.637 90.3,38.582 90.3,38.425 91.825,36.9 92.4,36.9 93.825,35.475 93.825,34.095 93.58,33.85 R118.1@93.075,33.85 v1(93.075,33.175) R146.1@93.075,32.5
  Bottom Layer w0.11: v1(93.075,33.175) R300.2@93.075,33.85
ETH1.TX_CTL: R165.1 U27.Y12 | length 6.3
  Top Layer w0.09: 93.319,60.475 94.695,61.851 94.695,65.305 U27.Y12@94.4,65.6
  Top Layer w0.11: R165.1@93.319,60 93.319,60.475
ETH1.TXD0: R168.1 U27.T10 | length 15.6
  Top Layer w0.1: v2(92.4,68.4) U27.T10@92.8,68.8
  Bottom Layer w0.11: R168.1@90.137,54.712 92.61,57.185 92.61,67.163 92.845,67.398 92.845,67.955 92.745,68.055 v2(92.4,68.4)
ETH1.TXD1: R174.1 U27.V11 | length 12.7
  Top Layer w0.09: v2(93.05,66.775) 93.294,67.019 93.364,67.019 93.545,67.2 U27.V11@93.6,67.2
  Bottom Layer w0.11: R174.1@91.512,55.437 92.82,56.745 92.82,66.545 v2(93.05,66.775)
ETH1.TXD2: R179.1 U27.U11 | length 15.3
  Top Layer w0.1: v2(93.2,67.6) U27.U11@93.6,68
  Bottom Layer w0.11: R179.1@90.787,54.062 93.03,56.305 93.03,66.21 93.475,66.655 93.475,67.048 93.21,67.313 93.21,67.59 v2(93.2,67.6)
ETH1.TXD3: R186.1 U27.T11 | length 15.1
  Top Layer w0.1: v2(93.2,68.4) U27.T11@93.6,68.8
  Bottom Layer w0.11: R186.1@92.162,54.787 93.24,55.865 93.24,66.13 93.75,66.64 93.75,67.298 93.595,67.453 93.595,68.005 v2(93.2,68.4)
ETH1i.CLK125: R93.2 R177.1 | length 30.1
  Top Layer w0.11: v1(78.575,28.575) 79.6,27.55 80.625,27.55 80.925,27.25 R177.1@80.925,26.7 ; R93.2@93.25,40.15 93.25,39.45 94.725,37.975 94.725,33.525 94.35,33.15 v1(94.35,32.575)
  Bottom Layer w0.11: v1(78.575,28.575) 79.925,29.925 79.925,30.72 82.305,33.1 87.35,33.1 87.875,32.575 v1(94.35,32.575)
ETH2.CLK: R196.1 U27.Y10 | length 70.4
  Top Layer w0.09: 90.116,60.475 90.116,60.768 92.325,62.976 92.325,64.997 92.603,65.275 92.744,65.275 92.8,65.331 U27.Y10@92.8,65.6
  Top Layer w0.11: v1(56.525,22.375) R196.1@56.525,23.05 ; v1(75.425,34.45) 75.425,38.575 90.116,53.266 90.116,60.475
  Bottom Layer w0.11: v1(56.525,22.375) 56.525,20.925 58,19.45 67.525,19.45 75.425,27.35 v1(75.425,34.45)
ETH2.CLK125: R176.1 U27.AA8 | length 63
  Top Layer w0.09: 88.326,60.475 88.326,60.855 90.716,63.245 90.716,64.316 U27.AA8@91.2,64.8
  Top Layer w0.11: R176.1@55.925,26.7 55.925,27.15 55.5,27.575 54.625,27.575 53.975,28.225 53.975,34.75 55.25,36.025 59.2,36.025 61.8,38.625 71.738,38.625 88.326,55.213 88.326,60.475
ETH2.GTX_CLK: R161.1 U27.T9 | length 18.7
  Top Layer w0.1: v2(91.6,68.4) U27.T9@92,68.8
  Bottom Layer w0.11: R161.1@86.912,52.687 91.688,57.463 91.688,64.313 92.175,64.801 92.175,67.175 91.955,67.395 91.955,68.045 v2(91.6,68.4)
ETH2.MDC: R195.1 U27.AA10 U38.13 | length 56.7
  Top Layer w0.09: 90.87,60.475 90.87,60.765 92.765,62.66 92.765,64.346 92.825,64.406 92.825,64.775 U27.AA10@92.8,64.8
  Top Layer w0.11: U38.13@63.85,24.55 64.312,24.55 64.92,23.942 v1(64.92,23.55) R195.1@65.595,23.55 ; v1(81.1,41.95) 89.075,49.925 90.15,49.925 90.87,50.645 90.87,60.475
  Bottom Layer w0.11: v1(64.92,23.55) 66.45,23.55 74,31.1 74,34.85 v1(81.1,41.95)
ETH2.MDINT: R318.1 U27.Y9 U38.31 | length 64.5
  Top Layer w0.09: 88.673,60.475 88.673,60.8 90.896,63.022 90.896,64.241 91.13,64.475 91.36,64.475 91.785,64.9 91.785,65.385 U27.Y9@92,65.6
  Top Layer w0.11: U38.31@58.95,27.35 58.45,27.35 58.176,27.624 58.176,27.974 v1(58.15,28) 57.745,28.405 56.177,28.405 55.955,28.627 55.955,32.975 55.485,33.445 55.485,34.675 56.285,35.475 59.4,35.475 62.025,38.1 71.913,38.1 88.673,54.86 88.673,60.475
  Bottom Layer w0.11: v1(58.15,28) R318.1@58.15,28.725
ETH2.MDIO: R191.1 U27.U9 U38.14 | length 57.8
  Top Layer w0.1: v2(91.6,67.6) U27.U9@92,68
  Top Layer w0.11: U38.14@63.85,24.95 64.52,24.95 v1(64.92,24.55) R191.1@65.595,24.55
  Bottom Layer w0.11: v1(64.92,24.55) 66.55,24.55 72.825,30.825 72.825,39.25 91.266,57.691 91.266,64.36 91.95,65.044 91.95,66.925 91.755,67.12 91.755,67.39 91.6,67.545 v2(91.6,67.6)
ETH2.NRST: R205.1 U27.H2 U38.12 | length 112.3
  Top Layer w0.09: 81.172,75.439 81.234,75.439 81.254,75.459 ; 82.885,75.459 82.895,75.469 82.912,75.469 ; 86.115,75.475 86.125,75.475 U27.H2@86.4,75.2
  Top Layer w0.1: U38.12@63.85,24.15 64.275,24.15 64.48,23.945 64.48,23.02 64.95,22.55 65.575,22.55 R205.1@65.595,22.55 65.595,22.03 65.8,21.825 67.5,21.825 69.375,19.95 v1(69.375,17.975) ; v1(75.775,76.225) 76.561,75.439 81.172,75.439 ; 81.254,75.459 82.885,75.459 ; 82.912,75.469 85.459,75.469 85.48,75.49 85.79,75.49 85.805,75.475 86.115,75.475
  Bottom Layer w0.1: v1(69.375,17.975) 69.025,18.325 53.6,18.325 49.415,22.51 49.415,32.415 49.425,32.425 49.425,32.761 56.639,39.975 61.502,39.975 71.66,50.133 71.66,70.123 71.65,70.133 71.65,70.416 70.991,71.075 70.991,73.553 71.613,74.175 73.725,74.175 v1(75.775,76.225)
ETH2.RX_CLK: R109.1 R135.1 R305.2 U27.AB8 | length 49.8
  Top Layer w0.09: 88.981,60.475 88.981,60.73 91.2,62.95 U27.AB8@91.2,64
  Top Layer w0.11: R135.1@63.075,32.5 v1(63.075,33.175) R109.1@63.075,33.85 62.45,33.85 62.45,36.6 63.45,37.6 72.175,37.6 88.981,54.406 88.981,60.475
  Bottom Layer w0.11: v1(63.075,33.175) R305.2@63.075,33.85
ETH2.RX_CTL: R110.1 R136.1 R304.2 U27.W9 | length 50.9
  Top Layer w0.09: 89.364,60.475 89.364,60.747 91.965,63.348 91.965,65.146 92.325,65.506 92.325,65.95 92.325,66.075 U27.W9@92,66.4
  Top Layer w0.11: R136.1@64.075,32.5 v1(64.075,33.175) R110.1@64.075,33.85 64.525,33.85 64.675,34 64.675,36.5 65.225,37.05 72.425,37.05 89.364,53.989 89.364,60.475
  Bottom Layer w0.11: v1(64.075,33.175) R304.2@64.075,33.85
ETH2.RXD0: R111.1 R137.1 R293.2 U27.W7 | length 47.8
  Top Layer w0.09: 87.214,60.475 87.214,60.921 89.745,63.452 89.745,64.271 89.925,64.451 89.925,65.925 U27.W7@90.4,66.4
  Top Layer w0.11: R137.1@65.275,32.5 v1(65.275,33.175) R111.1@65.275,33.85 ; v1(66.1,39.2) 67.7,40.8 71.25,40.8 87.214,56.764 87.214,60.475
  Bottom Layer w0.11: v1(65.275,33.175) 65.275,36.25 66.1,37.075 v1(66.1,39.2) 66.1,39.925 R293.2@66.125,39.95
ETH2.RXD1: R112.1 R138.1 R292.2 U27.Y7 | length 46.7
  Top Layer w0.09: 87.424,60.475 87.424,60.877 89.925,63.377 89.925,64.197 90.105,64.377 90.105,65.305 U27.Y7@90.4,65.6
  Top Layer w0.11: R138.1@66.275,32.5 v1(66.275,33.175) R112.1@66.275,33.85 ; v1(67.15,39.2) 68.225,40.275 71.3,40.275 87.424,56.399 87.424,60.475
  Bottom Layer w0.11: v1(66.275,33.175) 66.275,34.075 65.825,34.525 65.825,35.925 67.15,37.25 v1(67.15,39.2) R292.2@67.15,39.95
ETH2.RXD2: R113.2 R139.1 U27.AA7 | length 44.6
  Top Layer w0.09: 87.634,60.475 87.634,60.832 90.105,63.303 90.105,64.122 90.4,64.417 U27.AA7@90.4,64.8
  Top Layer w0.11: R139.1@67.275,32.5 v1(67.275,33.175) R113.2@67.275,33.85 ; v1(68.2,39.2) 68.775,39.775 71.505,39.775 87.634,55.905 87.634,60.475
  Bottom Layer w0.11: v1(67.275,33.175) 67.275,34.075 66.775,34.575 66.775,35.85 68.2,37.275 v1(68.2,39.2)
ETH2.RXD3: R114.1 R140.1 R303.2 U27.AB7 | length 43.1
  Top Layer w0.09: 87.87,60.475 87.87,60.813 90.4,63.343 U27.AB7@90.4,64
  Top Layer w0.11: R140.1@68.275,32.5 v1(68.275,33.175) R114.1@68.275,33.85 ; v1(69.225,39.2) 71.611,39.2 87.87,55.458 87.87,60.475
  Bottom Layer w0.11: v1(68.275,33.175) R303.2@68.275,33.85 68.925,33.85 69.225,34.15 v1(69.225,39.2)
ETH2.TX_CTL: R164.1 U27.V9 | length 16.3
  Top Layer w0.09: v2(91.525,66.825) 91.575,66.825 91.95,67.2 U27.V9@92,67.2
  Bottom Layer w0.11: R164.1@86.262,53.337 90.898,57.973 90.898,64.513 91.401,65.016 91.401,66.426 91.47,66.496 91.47,66.77 v2(91.525,66.825)
ETH2.TXD0: R167.1 U27.Y8 | length 11
  Top Layer w0.09: v2@90.865,65.226 v2(90.846,65.245) U27.Y8@91.2,65.6
  Bottom Layer w0.11: R167.1@87.712,56.087 90.175,58.55 90.175,64.575 v2(90.846,65.245)
ETH2.TXD1: R173.1 U27.V8 | length 14.5
  Top Layer w0.09: v2(90.846,66.845) U27.V8@91.2,67.2
  Bottom Layer w0.11: R173.1@86.987,54.712 90.525,58.25 90.525,64.423 91.201,65.098 91.201,66.49 v2(90.846,66.845)
ETH2.TXD2: R178.1 U27.U8 | length 13
  Top Layer w0.09: v2(90.846,67.645) U27.U8@91.2,68
  Bottom Layer w0.11: R178.1@87.062,56.737 89.425,59.1 89.425,64.495 90.233,65.303 90.233,67.018 90.423,67.208 90.423,67.223 v2(90.846,67.645)
ETH2.TXD3: R185.1 U27.T8 | length 16
  Top Layer w0.1: v2(90.8,68.4) U27.T8@91.2,68.8
  Bottom Layer w0.11: R185.1@86.337,55.362 89.8,58.825 89.8,64.587 90.433,65.22 90.433,66.935 90.748,67.25 91.075,67.25 91.245,67.42 91.245,67.955 v2(90.8,68.4)
ETH3.GTX_CLK: R163.1 U27.V13 | length 12.3
  Top Layer w0.09: U27.V13@95.2,67.2 95.541,67.541 95.541,67.734 v2(95.6,67.793)
  Bottom Layer w0.11: v2(95.6,67.793) 95.6,67.709 95.8,67.509 95.8,65.939 95.975,65.765 R163.1@95.975,56.4
ETH3.MDINT: R314.1 U27.V15 U40.31 | length 48
  Top Layer w0.09: 95.975,60.475 96.315,60.815 96.315,64.385 96.475,64.545 96.475,66.875 U27.V15@96.8,67.2
  Top Layer w0.11: 95.975,60.475 95.45,59.95 95.45,46.072 105.485,36.037 105.485,33.365 105.75,33.1 105.75,30.103 105.911,29.943 105.911,28.672 106.072,28.511 107.639,28.511 v1(108.176,27.974) 108.176,27.624 108.45,27.35 U40.31@108.95,27.35
  Bottom Layer w0.11: R314.1@108.15,28.725 108.176,28.699 v1(108.176,27.974)
ETH3.RX_CLK: R119.1 R147.1 R299.2 U27.Y13 | length 56.1
  Top Layer w0.09: 93.758,60.475 94.875,61.593 94.875,65.275 U27.Y13@95.2,65.6
  Top Layer w0.11: 93.758,60.475 93.758,43.567 v1(100.525,36.8) ; R147.1@113.075,32.5 R119.1@113.075,33.85
  Bottom Layer w0.11: v1(100.525,36.8) 110.22,36.8 110.422,36.597 110.461,36.558 110.59,36.558 110.926,36.894 111.054,36.894 111.183,36.765 111.183,36.637 110.315,35.769 110.315,35.64 110.444,35.511 110.572,35.511 111.44,36.379 111.569,36.379 111.698,36.251 111.698,36.122 110.83,35.254 110.83,35.125 110.959,34.997 111.087,34.997 111.955,35.865 112.084,35.865 112.213,35.736 112.213,35.607 111.345,34.739 111.345,34.611 111.473,34.482 111.602,34.482 112.005,34.885 112.134,34.885 112.281,34.739 112.32,34.7 112.445,34.575 112.445,33.929 112.524,33.85 R299.2@113.075,33.85 v1(113.075,33.175)
ETH3.RX_CTL: R120.1 R148.1 R298.2 U27.W13 | length 54.3
  Top Layer w0.11: v2(94.65,66) 94.606,66 94.662,66.055 94.855,66.055 U27.W13@95.2,66.4 ; R148.1@114.075,32.5 R120.1@114.075,33.85
  Bottom Layer w0.11: v2(94.65,66) 94.65,41.675 99,37.325 111.521,37.325 112.238,37.325 112.329,37.234 112.329,36.22 112.42,36.129 112.602,36.129 112.693,36.22 112.693,37.234 112.784,37.325 112.839,37.325 113.15,37.325 114.725,35.75 114.725,34 114.575,33.85 R298.2@114.075,33.85 v1(114.075,33.175)
ETH3.RXD0: R121.1 R149.1 R307.2 U27.T12 | length 54.2
  Top Layer w0.1: v2(94,68.4) U27.T12@94.4,68.8
  Top Layer w0.11: R149.1@115.075,32.5 v1(115.075,33.175) R121.1@115.075,33.85
  Bottom Layer w0.11: v2(94,68.4) 94.382,68.017 94.382,66.371 94.261,66.25 94.261,41.464 99.557,36.168 109.229,36.168 112.766,32.631 114.944,32.631 R307.2@115.01,32.565 ; R307.2@115.075,32.5 R307.2@115.01,32.565 ; v1(115.075,33.175) 115.075,32.631 R307.2@115.01,32.565
ETH3.RXD1: R122.1 R150.1 R306.2 U27.U13 | length 54.2
  Top Layer w0.11: v2(94.8,66.8) 94.8,67.602 95.198,68 U27.U13@95.2,68 ; R150.1@116.075,32.5 v1(116.075,33.175) R122.1@116.075,33.85
  Bottom Layer w0.11: v2(94.8,66.8) 94.8,66.752 95.025,66.527 95.025,60.475 95.025,41.9 99.15,37.775 113.475,37.775 115.159,36.091 115.159,34.091 v1(116.075,33.175) R306.2@116.075,32.5
ETH3.RXD2: R123.2 R151.1 U27.T13 | length 55.3
  Top Layer w0.11: v2(94.8,69.075) U27.T13@95.2,68.8 ; R151.1@117.075,32.5 v1(117.075,33.175) R123.2@117.075,33.85
  Bottom Layer w0.11: v2(94.8,69.075) 94.8,67.495 95.077,67.217 95.275,67.019 95.275,60.475 95.275,42.275 99.35,38.2 113.625,38.2 115.584,36.241 115.584,34.666 v1(117.075,33.175)
ETH3.RXD3: R124.1 R152.1 R297.2 U27.U14 | length 55.8
  Top Layer w0.09: U27.U14@96,68 U27.U14@96,68.025
  Top Layer w0.1: v2(95.6,68.4) U27.U14@96,68
  Top Layer w0.11: R152.1@118.075,32.5 v1(118.075,33.175) R124.1@118.075,33.85
  Bottom Layer w0.11: v2(95.6,68.4) 95.245,68.045 95.245,67.646 95.506,67.386 95.506,60.475 95.506,42.652 99.508,38.65 113.975,38.65 116.55,36.075 116.55,34.375 117.075,33.85 R297.2@118.075,33.85 v1(118.075,33.175)
ETH3.TX_CTL: R166.1 U27.T14 | length 35.7
  Top Layer w0.09: 94.25,60.475 95.275,61.5 95.275,65 95.495,65.22 95.495,66.775 95.495,67.2 95.858,67.563 96.163,67.563 96.4,67.8 96.4,68.048 96,68.448 U27.T14@96,68.8
  Top Layer w0.11: 94.25,60.475 94.125,60.35 94.125,44 97.598,40.527 v1(99.915,40.527)
  Bottom Layer w0.11: v1(99.915,40.527) 100.973,40.527 101.9,39.6 R166.1@101.9,39.55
